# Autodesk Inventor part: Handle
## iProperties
Created: 2008-10
Part Number: Handle
Document SubType Name: Modeling
Designer: the-dude
Density: 1 g/cm^3
Author: the-dude
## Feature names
1. Handle outline [Revolution]
2. Endcap screw hole [Revolution]
3. Revolution3
4. Rectangular Pattern1
5. Extrusion2
6. Extrusion3
